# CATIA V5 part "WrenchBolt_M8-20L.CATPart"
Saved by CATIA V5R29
Part number: WrenchBolt_M8-20L_Cover
Bounding box of the stored display mesh (mm): x -6.635 to 6.635, y -6.625 to 6.625, z -20 to 8
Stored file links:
  C:\Users\Administrator\Desktop\프로젝트\Boxfold\Braket\WrenchBolt_M8-20L.CATPart
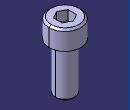
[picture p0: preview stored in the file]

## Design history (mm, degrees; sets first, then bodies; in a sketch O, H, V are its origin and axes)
Body1 (main body)
  Sketch1 on xy-plane, origin (0, 0, 0), H (1, 0, 0), V (0, 1, 0)
    circle A1 centre (0, 0) radius 6.635
    radius A1 = 6.635
  Pad1: profile Sketch1, direction (0, 0, 1), length 8
  Sketch2 on start face of Pad1, origin (0, 0, 0), H (1, 0, 0), V (0, -1, 0)
    circle A1 centre (0, 0) radius 4
    radius A1 = 4
  Pad2: profile Sketch2, direction (0, 0, -1), length 20
  Sketch3 on end face of Pad1, origin (0, 0, 8), H (1, 0, 0), V (0, 1, 0)
    point P1 (3.0475, 0)
    construction circle A1 centre (0, 0) radius 3.5189
    construction circle A2 centre (0, 0) radius 3.0475
    point P2 (3.0475, -1.7595)
    point P3 (3.0475, 1.7595)
    point P4 (0, 3.5189)
    point P5 (-3.0475, 1.7595)
    point P6 (-3.0475, -1.7595)
    point P7 (0, -3.5189)
    line L1 (3.0475, -1.7595) -> (3.0475, 1.7595)
    line L2 (3.0475, 1.7595) -> (0, 3.5189)
    line L3 (0, 3.5189) -> (-3.0475, 1.7595)
    line L4 (-3.0475, 1.7595) -> (-3.0475, -1.7595)
    line L5 (-3.0475, -1.7595) -> (0, -3.5189)
    line L6 (0, -3.5189) -> (3.0475, -1.7595)
    construction line L7 (0, 0) -> (3.0475, 0)
    radius A2 = 3.0475
    coincidence: A1 P2, A1 P3, A1 P4, A1 P5, A1 P6, A1 P7
    tangency: A2 L1, A2 L2, A2 L3, A2 L4, A2 L5, A2 L6
    midpoint: P1 L1
    horizontal: L7 H
  Pocket1: profile Sketch3, direction (0, 0, -1), length 4
  Thread1: "M8", diameter 8, depth 20, pitch 1.25, on face of Pad2 from Sketch2.A1, from end face of Pad2
  Chamfer1: length 0.8, angle 45, on end face of Pad2; edge [face of Pad1 from Sketch1.A1 | end face of Pad1]
  Fillet1: radius 0.4, on edge [start face of Pad1 | face of Pad2 from Sketch2.A1]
